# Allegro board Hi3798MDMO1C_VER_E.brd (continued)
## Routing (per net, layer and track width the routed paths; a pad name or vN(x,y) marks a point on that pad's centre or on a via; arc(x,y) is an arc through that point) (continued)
$4N687: length 3.1
  TOP w0.508: U11.1 96.09,54.12 C8.1 R73.2
$4N714: length 4.2
  TOP w0.508: U13.6 82.67,23.38 R110.1 83.93,23.38 R13.2 R101.1 C82.1
$4N715: length 94.6
  TOP w0.127: R23.1 80.94,55.4 80.58,55.75 C72.1 80.58,56.45 82.26,58.12 106.79,58.12 109.23,55.68 109.23,49.07 112.11,46.19 112.11,40.6 109.23,37.72 109.23,26.54 100.06,17.36 90.19,17.36 85.88,21.67 R102.2 84.3,21.67 84.28,21.69 C45.1
$4N716: length 0.9
  TOP w0.127: R102.1 84.75,22.54 R110.2
$4N724: length 3.9
  TOP w0.508: v1(82.55,27.01) 82.47,26.93 U13.1
  BOTTOM w0.508: v1(82.55,27.01) 82.55,26.98 82.97,26.57 R5.2 83.93,26.57 C5.1
$4N894: length 1.4
  TOP w0.508: R70.2 95.79,56.45 R7.1
$4N901: length 4
  TOP w0.508: U14.5 11.27,57.83 10.82,57.37 R100.1 10.8,56.83 9.77,56.83 R105.1
$4N903: length 5.9
  TOP w0.254: v1(15.09,66.33) 15.08,66.32 U14.1
  BOTTOM w0.254: v1(17.14,64.63) 17.14,65.14 15.95,66.33 v1(15.09,66.33) 14.59,66.84 R95.1
$4N904: length 0.9
  TOP w0.254: R104.1 12.69,55.89 C83.2
$4N905: length 3.9
  TOP w0.254: U14.6 12.54,58.27 11.89,57.62 C24.1 C83.1
$4N906: length 3.3
  TOP w0.254: R4.2 14.53,57.22 13.81,57.93 U14.7
$4N919: length 2.9
  TOP w0.254: U14.8 15.08,58.35 C44.1
$4N923: length 0.9
  BOTTOM w0.254: R95.2 13.14,67.65 C65.1
$4N925: length 1.6
  BOTTOM w0.254: C65.2 11.52,66.82 v1(11.52,66.83)
$5N541: length 3.6
  TOP w0.305: R144.2 20.28,58.19 21.11,57.37 Q4.3 22.28,56.91 R118.2
$5N542: length 100.2
  TOP w0.127: v2(21.41,49.88) 21.31,49.98 21.31,52.33 23.5,54.51 23.5,57.67 R118.1 22.86,58.79 22.23,59.43 22.23,60.72 22.03,60.91 Q14.1 ; v1(60.96,11.55) 60.81,11.7 27.53,11.7 16.05,23.18 v1(15.49,23.18)
  TOP w0.203: Q13.1 64.28,11.69 v1(64.14,11.55)
  TOP w0.254: Q14.1 21.36,62.74 C6.2 ; v2(17.27,41.91) 16.81,41.45 16.81,33.06 v2(16,32.25)
  BOTTOM w0.127: v1(15.49,23.18) 15.49,31.74 v2(16,32.25) ; v2(21.41,49.88) 21.31,49.77 21.31,48.17 17.27,44.13 17.27,42.31 17.27,42.31 v2(17.27,41.91)
  BOTTOM w0.203: v1(60.96,11.55) v1(64.14,11.55)
$5N549: length 1.4
  TOP w0.254: R98.2 20.04,53.74 20.09,53.79 Q4.1
$6N188: length 2.8
  TOP w0.203: X2.3 81.18,40.11 C365.1 80.3,39.11 R14.2
$6N1407: length 1.9
  TOP w0.305: U1.E6 v2(61.22,52.23)
  BOTTOM w0.381: v2(61.22,52.23) 61.04,52.41 R173.1
$6N2001: length 2.4
  TOP w0.127: U1.Y17 v2(70.82,40.23)
  BOTTOM w0.127: R61.2 71.33,39.05 71.22,39.16 71.22,39.84 v2(70.82,40.23)
$6N2177: length 6.7
  TOP w0.127: R85.1 R24.1 77.21,47.39 72.38,47.39 U1.L19
$6N2378: length 2.4
  TOP w0.127: U1.N23 76.36,45.43 76.83,45.91 R68.2
$7N1408: length 1.2
  TOP w0.127: U1.G17 v2(70.82,50.63)
  BOTTOM w0.127: v2(70.82,50.63) 70.69,50.76 C250.2
$7N1639: length 3.8
  TOP w0.127: U1.D8 v2(63.62,53.04)
  BOTTOM w0.127: R82.2 65,54.92 64.64,54.56 R87.2 64.07,53.48 v2(63.62,53.04)
$7N1763: length 1.3
  TOP w0.127: U1.F20 v2(73.22,51.43)
  BOTTOM w0.127: v2(73.22,51.43) 73.37,51.59 R32.2
$7N1940: length 49.5
  TOP w0.127: v1(106.73,59.05) 79.84,59.05 78.89,58.11 R42.1 ; S2.1 112.52,54.77 112.1,55.19 112.1,57.92 111.51,58.5 v1(111.51,59.84) 111.51,60.5 111.98,60.97 S2.2 113.32,61.85 114.68,63.21 C34.1
  BOTTOM w0.127: v1(111.51,59.84) 110.73,59.05 v1(106.73,59.05)
$8N1506: length 1.3
  TOP w0.127: U1.W16 v2(69.22,40.24)
  BOTTOM w0.127: R45.1 69.17,40.29 v2(69.22,40.24)
$8N1694: length 11
  TOP w0.152: U1.AC8 63.21,37.43 63.21,37.06 63.32,36.95 63.32,36.65 63.18,36.51 63.06,36.51 62.92,36.36 62.92,36.16 63.06,36.02 63.18,36.02 63.32,35.88 63.32,35.74 63.18,35.6 63.06,35.6 62.92,35.46 62.92,35.26 63.06,35.12 63.18,35.12 63.32,34.98 63.32,34.62 63.14,34.44 63.14,34.14 63.32,33.97 63.32,33.75 63.14,33.58 63.14,33.3 63.32,33.12 63.32,28.38 63.16,28.23 R18.2
$8N1695: length 10.9
  TOP w0.152: U1.AB8 63.22,38.03 63.62,37.63 63.62,28.29 63.34,28.01 R35.2
$8N1696: length 12.3
  TOP w0.152: R36.2 59.99,27.97 62.11,30.1 62.11,36.96 62.29,37.13 62.29,37.74 62.06,37.97 62.06,38.46 62.42,38.82 U1.AA7
$8N1697: length 11.9
  TOP w0.152: R37.2 60.93,27.6 60.93,27.88 60.76,28.06 60.76,28.31 62.42,29.97 62.42,36.83 62.59,37.01 62.59,37.88 62.42,38.05 U1.AB7
$9N2352: length 1.4
  TOP w0.305: U1.T19 v2(72.42,43.44)
  BOTTOM w0.381: C255.2 72.87,42.98 v2(72.42,43.44)
$11N1183: length 1.3
  TOP w0.165: U3.L8 v2(42.21,43.83)
  BOTTOM w0.127: R46.2 41.99,44.05 v2(42.21,43.83)
$11N1256: length 4.7
  BOTTOM w0.381: R15.1 46.42,39.46 45.81,38.84 44.63,38.84 44.23,39.24 C328.1 R11.2
$12N1465: length 2.9
  TOP w0.127: U6.L8 42.21,27.42 v2(42.21,28.22)
  BOTTOM w0.127: R71.2 41.15,28.5 41.43,28.22 v2(42.21,28.22)
$12N1636: length 4.1
  BOTTOM w0.203: R17.1 44.96,29.29 44.96,28.7 44.63,28.37 43.34,28.37 R16.2
  BOTTOM w0.254: R17.1 44.84,29.87 44.79,29.92 C330.1
$13N604: length 2.9
  TOP w0.089: U22.K2 100.91,31.25 101.57,31.25
  TOP w0.127: v2(101.59,31.25) 101.57,31.25
  BOTTOM w0.203: C124.1 100.96,31.89 v2(101.59,31.25) 101.97,31.63 C123.1
$13N727: length 2.9
  TOP w0.127: U19.39 99.16,22.88 v1(99.31,22.72)
  BOTTOM w0.127: R57.1 98.91,22.32 v1(99.31,22.72)
$13N772: length 2.1
  TOP w0.127: v2(98.64,22.82) 98.66,22.85 U19.38
  BOTTOM w0.127: R80.2 99.29,23.46 98.65,22.82 v2(98.64,22.82)
$14N447: length 2.2
  TOP w0.254: U26.3 83.05,72.06 v1(83.34,71.78)
  BOTTOM w0.254: R220.1 83.02,71.45 v1(83.34,71.78)
$14N448: length 3.3
  TOP w0.254: U26.4 79.65,72.35 v1(80.34,73.04)
  BOTTOM w0.254: v1(80.34,73.04) 81.38,72 R106.2
$14N684: length 4.2
  TOP w0.203: C70.1 73.03,68.06 J28.9
$14N685: length 5.3
  TOP w0.203: C62.1 69.62,69.08 70,68.7 70,68.57 70.18,68.39 73.13,68.39 73.51,68.77 J28.8
$15N955: length 5.2
  BOTTOM w0.254: Q2.1 100.74,9.96 99.39,9.96 99.39,9.97 98.68,9.97 R31.2
$15N957: length 1.8
  TOP w0.127: Q1.1 114.95,14.69 R22.2
$16N873: length 8.9
  TOP w0.254: R66.1 R90.2 92.98,64.75 C363.1 92.82,64.86 R229.1 90.93,65.45 90.93,67.17 91.5,67.74 U5.5
$16N884: length 3.4
  TOP w0.254: C32.1 95.05,66.44 U5.7
$16N889: length 2.1
  TOP w0.254: C33.2 91.88,67.09 U5.6
$16N895: length 2.7
  TOP w0.254: U5.8 98.45,66.44 C32.2
$16N998: length 2
  TOP w0.254: R43.2 102.26,66.58 R48.2 102.27,66.58 R44.1
$16N1000: length 2.5
  TOP w0.254: U5.11 100.51,68.39 R43.1
$16N1002: length 1.3
  TOP w0.254: R193.1 89.47,65.6 C351.2
$16N1003: length 3.7
  TOP w0.254: U5.2 92.19,69.69 91.93,69.43 C55.1 90.07,69.43 R27.2
$16N1006: length 3.7
  TOP w0.254: R27.1 R19.1 88.37,68.01 C317.1 88.37,66.92 R193.2
$16N1021: length 8.5
  TOP w0.254: v1(95,69.46) 95,69.43 94.61,69.04 U5.3 92.35,69.04 91.93,68.62 C55.2 90.86,68.62 90.38,68.14 R19.2
  BOTTOM w0.254: R146.1 93.36,70.03 R74.2 94.41,70.05 v1(95,69.46)
$16N1028: length 3.2
  TOP w0.254: R28.1 102.26,69.79 C54.2 100.64,69.79 100.55,69.69 U5.13
$16N1029: length 7.7
  TOP w0.254: R20.1 102.08,68.53 101.64,68.97 C54.1 100.31,68.97 100.24,69.04 U5.12 98.3,69.04 v1(97.69,69.65)
  BOTTOM w0.254: R145.1 99,70.04 R72.1 98.09,70.05 v1(97.69,69.65)
$16N1040: length 14.7
  TOP w0.254: R194.2 105.27,70.75 105.27,63.65 103.13,61.51 C350.1
$16N1041: length 4
  TOP w0.254: R20.2 R28.2 103.05,70.75 C316.1 R194.1
$17N163: length 3.5
  TOP w0.508: T2.7 v1(48.9,64.62)
  BOTTOM w0.381: C297.1 48.42,64.13 v1(48.9,64.62) 49.38,64.13 C154.1
$17N165: length 3.7
  TOP w0.381: R67.1 38.08,73.62 38.56,74.11 38.56,74.59 38.43,74.71 J25.9
$17N170: length 9.4
  TOP w0.381: R79.1 53.52,72.09 J25.11
$17N171: length 12.9
  BOTTOM w0.508: R270.2 47.82,75.06 47.82,79.54 J25.8 47.83,81.58 J25.7
$17N172: length 4.7
  TOP w0.457: v1(41.29,70.34) 42.11,70.34 42.55,70.78 T2.15
  BOTTOM w0.508: v1(41.29,70.34) 41.29,71.15 41.84,71.7 R271.2
$17N173: length 4.7
  TOP w0.457: T2.10 48.9,70.78 48.46,70.34 v1(47.64,70.34)
  BOTTOM w0.508: R269.2 48.19,71.7 47.64,71.15 v1(47.64,70.34)
$17N175: length 12.4
  TOP w0.254: T2.9 50.17,72.68 49.81,73.03 47.95,73.03 46.53,74.45 46.23,74.76 46.23,77.72 46.61,78.11 46.99,78.11 47.2,78.31 47.2,78.8 46.82,79.18 J25.6
$17N176: length 12.6
  TOP w0.254: T2.11 47.63,72.78 46.36,74.05 45.82,74.59 45.82,80.85 44.33,82.35 J25.3
$17N177: length 13.4
  BOTTOM w0.508: R270.1 51.02,69.69 49.11,69.69 R269.1 48.79,69.69 45.68,69.69 R272.1 45.36,69.69 42.76,69.69 R271.1 42.44,69.69 39.38,69.69 C23.1
$17N178: length 14.1
  TOP w0.254: J25.1 41.74,81.2 41.41,80.87 41.41,78.53 44.18,75.76 44.18,73.77 43.57,73.16 41.89,73.16 41.28,72.55 T2.16
$17N179: length 11
  TOP w0.254: J25.2 42.75,79.68 42.5,79.43 42.02,79.43 41.81,79.22 41.81,78.7 44.58,75.93 44.58,73.6 43.82,72.84 T2.14
$17N180: length 11.4
  BOTTOM w0.508: R272.2 45.52,77.6 44.78,78.33 J25.4 44.78,81.33 J25.5
$17N184: length 3.5
  TOP w0.508: T2.2 v1(42.55,64.62)
  BOTTOM w0.381: C307.1 43.03,64.13 v1(42.55,64.62) 42.07,64.13 C153.1
$17N255: length 6
  TOP w0.152: T2.1 41.28,62.29 v1(41.91,61.66)
  BOTTOM w0.152: R59.2 44.88,60.26 44.88,60.54 44.76,60.67 42.62,60.67 42.25,61.04 42.25,61.48 42.08,61.66 v1(41.91,61.66)
$17N256: length 6.2
  TOP w0.152: v1(43.18,61.69) 43.82,62.33 T2.3
  BOTTOM w0.152: R62.2 45.19,60.24 45.19,60.67 44.88,60.98 42.75,60.98 42.56,61.17 42.56,61.43 42.81,61.69 v1(43.18,61.69)
$17N257: length 5.3
  TOP w0.152: v1(48.28,61.69) 48.1,61.69 47.63,62.16 T2.6
  BOTTOM w0.152: R63.2 47.04,60.26 47.04,60.65 47.35,60.97 48.61,60.97 48.8,61.16 48.8,61.46 48.56,61.69 v1(48.28,61.69)
$17N258: length 5.3
  TOP w0.152: v1(49.55,61.72) 49.72,61.72 50.17,62.17 T2.8
  BOTTOM w0.152: R64.2 47.35,60.24 47.35,60.53 47.48,60.66 48.73,60.66 49.1,61.03 49.1,61.52 49.3,61.72 v1(49.55,61.72)
$19N506: length 2
  TOP w0.254: D19.1 28.26,68.59 29.17,69.49 R268.1

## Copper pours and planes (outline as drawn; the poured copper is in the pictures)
1V1_CORE on TOP (solid shape): 82.42,32.88 82.42,31.49 81.96,31.02 78.45,31.02 78.23,30.81 78.23,26.91 77.98,26.66 76.23,26.66 76.11,26.79 76.11,33.1 76.26,33.25 82.06,33.25
1V1_CORE on TOP (solid shape): 68.54,48.79 68.54,48.76 68.54,48.75 68.52,48.62 68.55,48.49 68.56,48.47 68.56,47.99 68.55,47.98 68.52,47.83 68.55,47.69 68.56,47.67 68.56,47.19 68.55,47.18 68.52,47.03 68.55,46.89 68.56,46.87 68.56,46.39 68.55,46.38 68.52,46.23 68.55,46.09 68.56,46.07 68.56,45.59 68.55,45.58 68.52,45.43 68.55,45.29 68.56,45.27 68.56,45.24 69.23,44.56 69.23,43.7 70.21,42.72 71.15,42.72 72.09,41.78 72.09,41.02 72.01,40.94 71.96,40.93 71.91,40.92 71.33,40.92 71.28,40.93 70.36,40.93 70.31,40.92 69.93,40.92 66.4,44.45 64.75,44.45 64.57,44.63 64.57,46.53 64.68,46.78 64.57,47.02 64.57,47.15 64.65,47.23 65.27,47.23 65.32,47.18 65.33,47.16 65.33,47.13 65.32,46.98 65.39,46.84 65.39,46.43 65.32,46.23 65.39,46.04 65.39,45.95 65.46,45.87 66.63,45.87 66.71,45.95 66.71,46.13 66.73,46.23 66.71,46.34 66.71,46.93 66.73,47.03 66.71,47.14 66.71,47.73 66.86,47.88 66.88,47.88 67.16,48.12 67.08,48.48 67.08,48.48 67.06,48.52 67.06,48.74 67.14,48.82 68.51,48.82
1V1_CORE on BOTTOM (solid shape): 72.65,42.01 72.65,41.51 73.26,40.91 73.76,40.91 74.5,40.16 74.5,40.15 78.62,36.04 78.62,33.57 79,33.19 79,31.39 78.77,31.16 76.01,31.16 75.83,31.34 75.83,33.52 78.23,33.52 78.23,33.9 77.85,33.9 77.85,33.52 75.83,33.52 75.83,34.13 78.18,34.13 78.18,34.46 77.85,34.46 77.85,34.13 75.83,34.13 75.83,34.77 74.81,35.79 74.81,37.71 73.41,39.11 74.42,39.11 74.42,38.98 74.55,38.85 74.68,38.85 74.8,38.98 74.8,39.11 74.68,39.23 74.55,39.23 74.42,39.11 73.41,39.11 72.57,39.95 72.4,39.95 71.78,40.57 70.71,40.57 69.77,41.52 69.77,42.07 69.78,42.09 70.62,42.09 70.72,42.19 70.72,42.77 70.77,42.82 71.84,42.82
1V1_CORE on BOTTOM (solid shape): 67.7,49.1 67.7,48.51 67.77,48.44 68.59,48.44 68.66,48.36 68.66,45.72 67.8,44.86 66.17,44.86 65.67,44.35 65.67,44.14 64.93,44.14 64.83,44.25 64.57,44.25 64.54,44.25 64.5,44.26 64.45,44.25 64.42,44.25 64.27,44.25 64.24,44.27 64.24,44.44 65.02,44.44 65.02,44.69 64.64,44.69 64.64,44.44 64.24,44.44 64.24,44.73 64.72,45.2 67.44,45.2 67.44,45.58 66.67,45.58 66.67,45.2 64.72,45.2 64.93,45.41 64.93,46.85 65.41,46.85 65.41,47.11 65.15,47.11 65.15,46.85 64.93,46.85 64.93,47.5 64.98,47.55 65.49,47.55 65.64,47.4 65.64,46.23 65.78,46.09 67.13,46.09 67.16,46.13 67.16,46.6 67.69,46.6 67.69,46.73 68.33,46.73 68.33,47.11 67.94,47.11 67.94,46.73 67.69,46.73 67.69,47.36 67.44,47.36 67.44,46.6 67.16,46.6 67.16,48.14 67.17,48.17 67.18,48.24 67.17,48.3 67.16,48.33 67.16,48.94 67.18,49.04 67.19,49.07 67.21,49.1 67.23,49.11 67.26,49.12 67.28,49.12 67.67,49.12
1V1_CPU on TOP (solid shape): 93.5,53.3 93.5,48.86 93.13,48.49 86.43,48.49 86.17,48.75 86.17,53.01 86.18,53.02 86.18,53.28 86.63,53.73 93.07,53.73
1V1_CPU on TOP (solid shape): 71.05,49.62 71.05,46.53 70.63,46.11 70.58,46.07 70.52,46 69.42,46 69.37,46.05 69.37,47.32 69.48,47.42 69.7,47.42 69.86,47.57 69.86,47.64 69.87,47.65 69.93,47.83 69.87,48.02 69.86,48.03 69.86,48.11 69.7,48.26 69.42,48.26 69.37,48.31 69.37,48.71 69.38,48.73 69.4,48.75 69.56,49.04 69.4,49.32 69.38,49.34 69.37,49.37 69.37,49.48 69.69,49.8 70.87,49.8
1V1_CPU on BOTTOM (solid shape): outline of 82 points within 69.81,46.04 90.68,50.97
1V5_DDR3 on TOP (solid shape): 17.64,53.6 18.23,53 18.23,46.8 17.88,46.45 15.32,46.45 15.26,46.51 15.26,48.25 17.78,48.25 17.78,48.5 17.4,48.5 17.4,48.25 15.26,48.25 15.26,48.69 15.2,48.76 17.78,48.76 17.78,49.14 17.4,49.14 17.4,48.76 15.2,48.76 15.08,48.87 15.08,53.33 15.35,53.6 16.82,53.6
1V5_DDR3 on TOP (solid shape): outline of 110 points within 59.77,39.68 68.23,48.84
1V5_DDR3 on BOTTOM (solid shape): 64.6,42.82 64.6,41.99 64.67,41.93 64.8,41.93 64.81,41.94 66.55,41.94 66.66,42.04 68.49,42.04 68.51,42.01 68.51,41.48 68.49,41.45 67.9,41.45 67.85,41.4 63.41,41.4 63.35,41.45 63.35,42.8 63.43,42.87 64.55,42.87
1V5_DDR3 on BOTTOM (solid shape): outline of 624 points within 16.71,24.44 62.36,53.76
3V3 on TOP (solid shape): 121.79,40.85 121.79,20.82 119.35,18.38 119.35,17.16 119.1,16.91 117.53,16.91 117.31,17.12 117.31,18.85 119.58,21.13 119.58,40.85 119.74,41.01 121.64,41.01
3V3 on TOP (solid shape): 80.91,23.83 80.91,22.72 80.75,22.57 80.24,22.57 80.14,22.47 80.14,22.35 80.14,22.34 80.14,21.28 80.07,21.21 76.63,21.21 76.56,21.28 76.39,21.45 76.39,21.71 79.63,21.71 79.63,22.09 79.38,22.09 79.38,21.71 76.39,21.71 76.39,23.79 76.54,23.94 80.8,23.94
3V3 on TOP (solid shape): 107.58,54.77 107.58,51.56 106.02,50 99.98,50 99.79,50.19 99.79,50.38 101.19,50.38 101.19,50.69 100.94,50.69 100.94,50.38 100.66,50.38 100.66,50.69 100.41,50.69 100.41,50.38 99.79,50.38 99.79,51.27 99.54,51.52 99.54,52.47 99.57,52.49 105.24,52.49 105.63,52.88 105.63,54.74 105.81,54.93 107.42,54.93
3V3 on TOP (solid shape): 9.22,62.08 9.22,60.12 8.82,59.73 6.38,59.73 5.94,59.3 5.94,54.54 6.51,53.98 6.51,50.88 6.85,50.54 8.51,50.54 8.64,50.41 8.64,49.52 8.51,49.39 5.72,49.39 5.46,49.13 4.56,48.23 4.56,48.23 3.89,47.56 3.89,41.05 3.63,40.78 1.72,40.78 1.45,41.05 1.45,49.77 6.1,49.77 6.1,50.15 5.71,50.15 5.71,49.77 1.45,49.77 1.45,54.6 5.59,54.6 5.59,54.98 5.21,54.98 5.21,54.6 1.45,54.6 1.45,55.11 5.59,55.11 5.59,55.49 5.21,55.49 5.21,55.11 1.45,55.11 1.45,58.81 4.94,62.31 8.98,62.31
3V3 on TOP (solid shape): 111.35,14.62 111.35,13.32 111.18,13.15 110.21,13.15 105.78,8.72 105.68,8.71 105.59,8.71 99.94,8.71 99.94,8.71 99.14,8.58 98.53,8.06 98.51,8.05 98.49,8.04 96.71,8.04 96.69,8.04 81.69,8.04 81.69,8.04 80.8,8.04 80.78,8.05 80.76,8.06 80.15,8.58 79.36,8.7 79.35,8.7 73.7,8.7 73.7,8.7 72.91,8.58 72.29,8.06 72.28,8.05 72.25,8.04 70.13,8.04 70.13,8.04 68.17,8.04 67.68,8.53 67.67,8.53 67.36,8.84 64.73,8.84 64.51,9.06 64.51,10.65 64.69,10.83 66.89,10.83 67.33,11.27 67.33,12.17 67.56,12.39 68.67,12.39 68.91,12.15 68.91,10.4 69.43,9.89 103.85,9.89 108.72,14.76 108.74,14.76 108.88,14.9 111.07,14.9
3V3 on BOTTOM (solid shape): 121.88,45.28 121.88,39.84 121.63,39.59 119.7,39.59 119.53,39.76 119.53,43.96 112.83,50.66 105.28,50.66 104.95,50.99 104.95,52.26 105.28,52.59 114.56,52.59
3V3 on BOTTOM (solid shape): 119.39,18.45 119.39,17.3 119.39,17.3 119.39,14.37 119.19,14.16 111.95,14.16 110.93,13.15 109.35,13.15 108.79,13.71 108.79,15.23 111.2,17.64 117.12,17.64 117.32,17.85 117.32,18.48 117.45,18.61 119.23,18.61
3V3 on BOTTOM (solid shape): 3.89,42.18 3.89,27.67 20.73,10.83 20.9,10.66 64.68,10.66 64.85,10.83 65.9,10.83 77.98,10.83 78.21,10.83 78.5,11.12 78.5,20.93 78.18,21.25 77.87,21.25 77,22.11 77,22.75 77.18,22.93 80.8,22.93 80.93,22.8 80.93,8.95 80.92,8.93 80.72,8.73 78.92,8.73 78.76,8.88 19.45,8.88 1.44,26.89 1.44,42.15 1.8,42.51 3.56,42.51
3V3_IR on TOP (solid shape): 121.29,15.62 122.43,15.62 122.69,15.37 122.69,8.94 122.48,8.73 120.97,8.73 120.59,9.11 120.59,13.31 120.47,13.43 119.38,13.43 118.5,14.31 118.5,14.85 121.79,14.85 121.79,15.23 121.41,15.23 121.41,14.85 119.38,14.85 119.38,15.23 119,15.23 119,14.85 118.5,14.85 118.5,15.37 118.62,15.49 119.26,15.49 119.77,16 120.91,16
3V3_MOS on TOP (solid shape): 16.64,18.28 16.64,17.52 15.88,17.52 14.86,18.53 14.86,18.66 15.24,19.04 15.88,19.04
3V3_MOS on TOP (solid shape): 114.88,69.54 114.88,69.13 115.46,68.55 115.46,65.74 115.34,65.62 113.87,65.62 113.79,65.7 113.79,69.59 113.87,69.66 114.76,69.66
3V3_MOS on TOP (solid shape): 111.51,57.77 111.51,50.99 115.19,47.31 115.19,44.69 114.86,44.36 113.23,44.36 112.9,44.7 112.9,46.37 109.98,49.29 109.98,56.88 109.98,56.88 105.78,61.08 105.78,61.82 106.17,62.21 107.07,62.21
3V3_MOS on TOP (solid shape): 118.67,38.14 118.67,25.42 103.4,10.15 72.29,10.15 72.14,10.3 72.14,10.3 69.92,12.52 66.44,12.52 66.37,12.59 66.37,14.34 66.68,14.65 70.75,14.65 74.13,11.28 96.16,11.28 96.37,11.21 96.57,11.28 102.01,11.28 107.59,16.86 107.62,16.86 109.15,18.39 109.3,18.48 109.39,18.62 116.48,25.72 116.48,38.12 116.79,38.42 118.39,38.42
3V3_MOS on TOP (solid shape): outline of 100 points within 60.64,45.24 72.68,52.81
3V3_MOS on BOTTOM (solid shape): 63.58,50.44 63.58,48.69 63.57,48.68 62.77,48.68 62.72,48.73 62.72,49.87 62.41,50.18 62.41,50.44 62.5,50.53 63.49,50.53
3V3_MOS on BOTTOM (solid shape): 74.56,46.02 74.56,44.61 74.46,44.51 73.73,44.51 73.66,44.59 73.65,44.59 73.63,44.6 73.63,45.27 73.41,45.49 72.27,45.49 72.17,45.59 72.17,46 72.22,46.05 74.53,46.05
3V3_MOS on BOTTOM (solid shape): 64.78,52.3 64.78,51.41 64.55,51.18 63.4,51.18 63.38,51.2 63.38,51.75 63.42,51.79 63.89,51.79 64.14,52.04 64.14,52.32 64.75,52.32
3V3_MOS on BOTTOM (solid shape): 118.69,42.19 118.69,36.74 118.52,36.57 116.48,36.57 116.31,36.74 116.31,40.81 113.26,43.86 111.25,43.86 109.52,42.13 106.94,42.13 106.76,42.31 106.76,43.63 109.26,46.13 114.76,46.13
3V3_MOS on BOTTOM (solid shape): 59.98,52.88 59.98,51.99 60.1,51.87 61.35,51.87 61.45,51.76 61.45,51.36 61.3,51.21 61.12,51.21 60.87,51.46 59.44,51.46 59.42,51.49 59.42,52.86 59.47,52.91 59.95,52.91
3V3_MOS on BOTTOM (solid shape): 66.01,53.76 66.01,53.35 66.17,53.19 66.66,53.19 66.68,53.16 66.68,52.63 67.06,52.25 67.06,51.84 66.99,51.76 65.95,51.76 65.92,51.79 65.92,52.96 65.64,53.24 65.28,53.24 65.26,53.26 65.26,53.8 65.31,53.85 65.92,53.85
3V3_MOS on BOTTOM (solid shape): outline of 88 points within 71.2,49.64 107.48,62.97
3V3_MOS_FLASH on TOP (solid shape): outline of 288 points within 92.84,30.17 109.38,42.85
3V3_MOS_FLASH on BOTTOM (solid shape): 110.19,41.19 110.19,39.57 109.74,39.12 105.5,39.12 105.32,39.3 105.32,41.06 105.59,41.32 110.06,41.32
3V3_MOS_FLASH on BOTTOM (solid shape): 95.96,30.83 95.96,30.46 95.86,30.37 94.51,30.37 92.12,27.98 92.12,26.33 93.97,24.49 96.79,24.49 96.9,24.37 96.9,23.99 97.03,23.87 97.92,23.87 98.04,23.99 98.04,24.5 98.17,24.63 99.44,24.63 99.57,24.5 99.57,23.99 99.44,23.87 98.93,23.87 98.68,23.61 98.68,23.36 98.17,22.85 96.9,22.85 96.65,22.6 96.27,22.6 96.01,22.85 94.11,22.85 93.73,22.47 93.73,21 94.08,20.64 102.18,20.64 102.39,20.44 102.39,19.73 102.08,19.42 91.14,19.42 90.8,19.75 90.8,21.73 91.05,21.97 91.31,21.97 91.95,22.61 91.95,23.1 91.82,23.23 97.79,23.23 97.79,23.61 97.41,23.61 97.41,23.23 91.82,23.23 91.11,23.95 91.11,28.62 93.41,30.93 95.85,30.93
3V3_WIFI on TOP (solid shape): 14.4,31.8 14.4,30.11 12.14,27.85 9.78,27.85 9.51,28.12 9.51,29.09 9.74,29.31 11.88,29.31 12.75,30.18 12.75,31.74 12.99,31.97 13.13,31.97 13.13,31.98 14.23,31.98
3V3_WIFI on BOTTOM (solid shape): 7.84,37.43 7.84,32.75 6.96,31.87 6.96,30.49 8.1,29.35 8.45,29.35 8.45,29.36 11.81,29.36 12.46,28.7 12.46,27.56 12.81,27.21 14.18,27.21 14.36,27.02 14.36,26.15 14.07,25.86 11.56,25.86 10.31,27.12 7.84,27.12 5.41,29.55 5.41,32.54 6.1,33.23 6.1,37.43 6.54,37.87 7.4,37.87
5V0 on TOP (solid shape): 15.18,73.01 15.18,71.99 16.11,71.06 18.62,71.06 19.23,70.45 19.23,66.77 20.68,65.32 20.68,61.45 20.46,61.24 18.12,61.24 17.78,61.57 17.78,63.46 18.67,64.35 18.67,65.45 17.78,66.33 17.78,68.7 17.65,68.82 16.13,68.82 15.98,68.68 15.98,66.85 15.81,66.67 15.22,66.67 15.19,66.68 15.14,66.69 15.09,66.7 15.04,66.69 14.99,66.68 14.96,66.67 14.66,66.67 14.4,66.41 14.4,63.84 13.52,63.84 13.51,63.84 13.41,63.84 13.41,68.32 14.22,68.32 14.22,68.7 13.84,68.7 13.84,68.32 13.41,68.32 13.41,68.74 12.53,69.62 8.4,69.62 8.24,69.77 8.24,70.09 11.05,70.09 11.05,70.35 10.79,70.35 10.79,70.09 10.54,70.09 10.54,70.35 10.29,70.35 10.29,70.09 8.24,70.09 8.24,73.57 8.51,73.84 14.35,73.84
5V0_MOS on TOP (solid shape): 21.88,60.49 21.88,59.23 21.68,59.03 19.16,59.03 18.99,59.2 18.99,60.45 19.14,60.6 21.77,60.6
5V0_MOS on TOP (solid shape): 84.68,71.03 84.68,69.2 84.3,68.82 82.1,68.82 81.56,69.36 81.56,70.4 81.69,70.53 83.24,70.53 83.79,71.08 84.63,71.08
5V0_MOS on BOTTOM (solid shape): 81.6,82.63 81.6,80.09 82.95,78.74 82.95,78.74 83.35,78.34 83.36,78.34 85.66,76.04 85.66,69.77 84.71,68.82 82.53,68.82 82.53,69.68 82.06,70.15 82.06,70.22 82.93,70.22 82.93,70.6 82.55,70.6 82.55,70.22 82.06,70.22 82.06,70.88 82.17,70.98 84.33,70.98 84.64,71.29 84.64,73.86 84.64,73.86 84.64,75.64 80.52,79.76 80.52,82.16 80.12,82.56 62.21,82.56 62.21,82.56 61.86,82.56 58.4,79.1 58.4,68.32 57.37,67.29 54.99,67.29 54.1,66.4 38.73,66.4 33.37,61.04 24.32,61.04 24.05,60.78 22.19,58.92 19.07,58.92 18.81,59.18 18.81,60.34 19.14,60.67 21.44,60.67 23.7,62.94 32.57,62.94 37.09,67.46 53.56,67.46 54.5,68.39 56.33,68.39 57.01,69.08 57.01,70.9 57.01,70.9 57.01,79.45 61.11,83.56 80.68,83.56
AVDD11_PLL012 on BOTTOM (solid shape): 70.36,45.9 70.36,45.34 70.51,45.2 71.15,45.2 71.22,45.13 71.22,44.31 71.25,44.29 71.59,44.29 71.61,44.27 71.61,43.59 71.58,43.56 70.77,43.56 70.75,43.59 70.75,44.6 70.54,44.81 69.88,44.81 69.81,44.88 69.81,45.9 69.83,45.92 70.34,45.92
AVDD11_USB3 on TOP (solid shape): 69.83,43.89 70.16,43.89 70.26,43.99 70.57,43.99 70.62,43.94 70.62,42.93 70.54,42.85 70.29,42.85 69.42,43.71 69.42,43.84 69.58,43.99 69.73,43.99
AVDD11_USB3 on BOTTOM (solid shape): 70.24,43.51 70.24,42.95 70.31,42.87 70.31,42.39 70.28,42.35 69.74,42.35 69.65,42.44 68.61,42.44 68.23,42.82 68.23,44.01 68.35,44.13 69.62,44.13
AVDD33_ADAC on BOTTOM (solid shape): 71.93,55.4 71.93,54.71 72.14,54.5 72.14,53.49 72.27,53.37 72.85,53.37 72.85,52.37 72.47,51.99 72.37,51.99 72.35,52.02 72.27,52.06 72.2,52.17 72.19,52.22 72.2,52.3 72.21,52.31 72.21,52.41 72.04,52.58 71.48,52.58 71.47,52.59 71.29,52.59 71.2,52.68 71.2,53.31 71.03,53.49 71.03,55.33 71.2,55.5 71.83,55.5
AVDD33_PLL01 on BOTTOM (solid shape): 76.03,46 76.03,43.76 75.77,43.51 73.74,43.51 73.36,43.89 72.22,43.89 72.14,43.97 72.14,44.32 72.28,44.46 73.6,44.46 74.02,44.04 74.84,44.04 75.04,44.25 75.04,46.02 75.06,46.05 75.98,46.05
AVDD33_USB2 on BOTTOM (solid shape): 75.49,48.69 72.36,48.69 72.36,48.69 72.25,48.69 72.18,48.77 72.18,49.17 72.21,49.18 72.28,49.21 72.34,49.25 72.48,49.25 72.57,49.19 72.69,49.16 72.87,49.16 73.01,49.3 74.1,49.3 74.33,49.52 75.49,49.52
GND on TOP (solid shape): 34.51,45.79 34.51,45.74 28.83,40.07 28.61,40.07 28.57,40.08 28.56,40.12 28.56,40.19 29.41,41.04 29.41,41.32 34.12,46.04 34.26,46.04
GND on TOP (solid shape): 38.73,42.82 38.76,42.81 38.78,42.77 38.78,42.35 38.68,42.25 37.46,42.25 28.59,33.39 28.54,33.38 28.51,33.42 28.51,33.46 28.75,33.7 28.75,34.2 37.37,42.82
GND on TOP (solid shape): 39.17,40.72 39.26,40.65 39.24,40.54 28.6,29.91 28.56,29.91 28.52,29.92 28.51,29.96 28.51,30.11 28.8,30.4 28.8,30.78 38.73,40.72
GND on TOP (solid shape): 79.37,51.3 79.46,51.24 79.44,51.12 79.43,51.11 77.35,51.11 76.61,50.37 76.23,50.37 76.19,50.38 76.17,50.42 76.17,50.46 77.01,51.3
GND on TOP (solid shape): 80.3,46.19 98.82,46.19 99.97,45.04 99.97,44.89 99.71,44.63 99.64,44.63 98.6,45.68 80.03,45.68 80.03,45.68 79.56,45.68 79.46,45.74 79.49,45.86 79.82,46.19 80.29,46.19
GND on TOP (solid shape): 36.32,44.86 36.41,44.79 36.39,44.69 28.76,37.05 28.65,37.03 28.58,37.12 28.56,37.12 28.56,37.51 35.9,44.86
GND on TOP (solid shape): 112.34,58.69 113.1,58.69 113.1,57.04 112.29,57.04 112.29,58 111.7,58.58 111.7,59.51 111.9,59.84 111.7,60.17 111.7,60.42 112.06,60.78 112.34,60.78
GND on TOP (solid shape): 35.05,70.47 35.05,70.3 35.05,70.3 35.05,68.21 34.91,68.07 34.18,68.07 33.89,68.36 33.89,68.7 34.67,68.7 34.67,69.46 34.42,69.46 34.42,68.7 33.89,68.7 33.89,69.04 33.88,69.04 33.88,69.15 33.89,69.15 33.89,69.98 33.73,70.14 33.73,70.54 33.82,70.62 34.89,70.62
GND on TOP (solid shape): 90.09,38 90.09,20.52 90.02,20.43 89.91,20.45 89.49,20.87 89.49,37.86 84.39,42.96 77.61,42.96 77.52,43.03 77.54,43.14 77.93,43.52 84.56,43.52
GND on TOP (solid shape): 29.47,73.56 29.47,72.21 29.48,72.2 31.18,72.2 31.21,72.18 31.23,72.15 31.23,71.39 31.21,71.35 31.18,71.34 29.48,71.34 29.23,71.09 28.77,71.09 27.33,72.53 27.33,73.52 27.6,73.8 29.24,73.8
GND on TOP (solid shape): 92.16,66.06 92.56,66.06 92.56,66.06 94.42,66.06 94.47,66.06 94.59,66.19 94.95,66.19 95.89,65.25 95.89,64.7 97.61,64.7 97.61,65.25 98.43,66.06 99.9,66.06 99.9,66.06 100.72,66.06 100.9,65.87 100.9,65.15 100.9,64.08 100.9,63.91 100.9,63.63 100.68,63.63 100.12,64.19 95.49,64.19 95.49,65.2 93.71,65.2 93.46,65.46 93.46,65.47 92.27,65.47 92.12,65.47 91.97,65.32 91.42,65.32 91.22,65.52 91.95,65.52 91.95,65.78 91.57,65.78 91.57,65.52 91.22,65.52 91.19,65.55 91.19,66.26 91.96,66.26
GND on TOP (solid shape): 41.88,42.97 41.88,42.95 42,42.77 42.21,42.7 42.27,42.67 42.4,42.41 42.6,42.33 42.67,42.3 42.7,42.23 42.7,42.08 41.25,40.63 40.43,40.63 40.33,40.69 40.36,40.8 40.92,41.37 41.13,41.37 41.25,41.48 41.26,41.48 41.62,41.84 41.62,42.34 41.6,42.37 41.6,43.1 41.75,43.1
GND on TOP (solid shape): 60.11,44.12 60.11,44.11 60.17,44.01 60.25,43.94 60.25,43.73 60.13,43.6 60.08,43.44 60.06,43.37 59.99,43.34 59.88,43.31 59.79,43.24 59.45,43.24 59.29,43.33 59.1,43.32 59,43.32 58.96,43.35 58.96,43.35 58.63,43.68 58.36,43.68 58.29,43.76 58.29,43.93 58.34,43.99 58.8,43.99 58.92,43.87 58.92,43.85 59.38,43.57 59.36,44.11 59.36,44.36 59.4,44.38 59.45,44.38 59.54,44.48 59.74,44.48
GND on TOP (solid shape): 25.01,75.81 25.01,75.22 24.88,75.1 24.88,74.8 24.88,74.79 24.85,74.73 24.85,74.67 24.85,74.09 24.85,74.02 24.88,73.97 24.88,73.95 24.88,73.75 24.88,73.74 24.85,73.68 24.85,73.62 24.85,73.04 24.85,72.97 24.88,72.92 24.88,72.9 24.88,72.74 24.97,72.65 24.97,68.83 27.59,66.21 32.4,66.21 38.11,60.49 50.9,60.49 54.3,63.9 63.72,63.9 66.55,61.06 66.55,60.81 66.87,60.49 67.13,60.49 67.2,60.41 67.2,60.16 67.52,59.84 67.78,59.84 68.4,59.22 68.4,58.92 68.71,58.6 69.02,58.6 69.57,58.04 69.57,57.74 69.89,57.42 70.19,57.42 70.33,57.28 70.33,56.66 70.31,56.59 70.24,56.56 63.38,63.41 54.44,63.41 50.98,59.96 38.05,59.96 32.26,65.75 26.53,65.75 24.19,68.09 24.19,72.5 24.29,72.6 24.29,72.9 24.3,72.92 24.32,72.97 24.33,73.04 24.33,73.62 24.32,73.68 24.3,73.74 24.29,73.75 24.29,73.95 24.3,73.97 24.32,74.02 24.33,74.09 24.33,74.67 24.32,74.73 24.3,74.79 24.29,74.8 24.29,75.1 24.18,75.21 24.18,75.96 24.32,76.1 24.71,76.1
GND on TOP (solid shape): outline of 116 points within 74.99,23.68 86,37.95
GND on TOP (solid shape): outline of 89 points within 21.01,55.11 68.68,75.81
GND on TOP (solid shape): 26.75,75.48 26.75,72.56 28.69,70.63 28.68,70.63 29.04,70.27 29.04,69.73 27.99,68.68 27.5,68.68 27.5,67.77 28.77,67.77 28.77,67.76 29.95,67.76 30.32,67.39 32.92,67.39 37.1,63.2 37.1,63.18 37.34,62.75 37.8,62.91 37.9,62.91 38.15,62.73 38.45,62.79 38.55,62.8 38.61,62.71 38.61,62.35 38.82,62.14 38.81,62.11 39.06,61.68 39.53,61.86 40.84,61.86 40.84,61.88 41.4,61.88 41.55,61.73 41.55,61.71 41.62,61.45 41.84,61.3 41.88,61.3 41.88,61.2 41.61,61.2 41.6,61.2 38.41,61.2 32.69,66.92 27.89,66.92 25.68,69.13 25.68,72.6 25.79,72.71 25.79,72.77 25.81,72.8 25.82,72.81 25.89,72.92 25.92,73.05 25.92,73.61 25.9,73.72 25.85,73.81 25.83,73.85 25.85,73.89 25.9,73.99 25.92,74.1 25.92,74.66 25.89,74.78 25.82,74.89 25.81,74.9 25.79,74.94 25.79,75.1 25.68,75.21 25.68,75.8 25.85,75.97 26.27,75.97
GND on TOP (solid shape): outline of 153 points within 116.23,8.5 119.34,13.45
GND on TOP (solid shape): outline of 137 points within 96.39,31.13 100.04,35.85
GND on TOP (solid shape): outline of 19011 points within 0.51,7.62 123.52,86.57
GND on BOTTOM (solid shape): 41.11,43.64 41.11,42.92 40.32,42.92 39.94,43.29 39.94,43.96 40.04,44.06 40.69,44.06
GND on BOTTOM (solid shape): 56.75,79.07 56.75,69.28 56.51,69.03 55.09,69.03 55.05,69.08 55.05,77.92 55.49,78.36 56.28,79.16 56.67,79.16
GND on BOTTOM (solid shape): 71.96,8.58 71.96,7.69 71.91,7.63 51.56,7.63 51.46,7.74 51.46,8.5 51.59,8.63 66.15,8.63 71.9,8.63
GND on BOTTOM (solid shape): outline of 178 points within 97.99,34.96 103.03,42.07
GND on BOTTOM (solid shape): outline of 14253 points within 0.51,7.62 123.52,86.57
FE_3V3 on BOTTOM (solid shape): 59.8,53.8 60.48,53.8 60.64,53.64 60.64,52.07 60.56,51.99 60.28,51.99 60.2,52.07 60.2,53.06 60.13,53.14 59.24,53.14 59.19,53.09 59.19,52.37 59.16,52.35 58.68,52.35 58.66,52.37 58.66,54.08 58.71,54.13 59.47,54.13
HDMI_TX_1V1 on BOTTOM (solid shape): 69.6,52.07 69.6,51.56 69.12,51.08 69.12,50.42 69.22,50.32 69.55,50.32 69.63,50.24 69.63,49.52 69.54,49.43 68.76,49.43 68.71,49.38 68.71,48.67 68.66,48.62 67.95,48.62 67.95,49.7 67.98,49.83 67.95,49.97 67.95,50.14 67.9,50.19 67.32,50.19 67.29,50.22 67.29,50.96 67.33,51 68.28,51 69.04,51.76 69.04,52.07 69.07,52.1 69.58,52.1
HDMI_TX_3V3 on BOTTOM (solid shape): 67.04,53.87 67.04,53.39 67.29,53.14 68.51,53.14 68.66,52.98 68.66,52.18 68.63,52.15 68.61,52.11 68.58,52.07 68.49,52.02 68.42,52.01 68.36,52.02 68.3,52.04 68.25,52.08 68.21,52.12 68.18,52.16 68.18,52.58 68.13,52.63 66.88,52.63 66.81,52.7 66.81,53.24 66.58,53.47 66.17,53.47 66.17,53.97 66.94,53.97
Net_278 on BOTTOM (solid shape): 52.91,79.93 50.25,79.93 50.25,81.2 52.91,81.2
Net_279 on BOTTOM (solid shape): 41.36,79.93 38.69,79.93 38.69,81.2 41.36,81.2
Net_280 on BOTTOM (solid shape): 51.9,81.71 49.23,81.71 49.23,82.98 51.9,82.98
Net_281 on BOTTOM (solid shape): 40.34,81.71 37.67,81.71 37.67,82.98 40.34,82.98
USB01_1V1 on BOTTOM (solid shape): 65.64,50.06 65.78,50.06 65.78,50.06 66.18,50.06 66.25,49.99 66.25,49.68 66.17,49.61 65.61,49.61 65.51,49.5 65.51,47.78 65.49,47.75 64.95,47.75 64.93,47.78 64.93,50.22 64.95,50.24 65.46,50.24
USB01_3V3 on BOTTOM (solid shape): 63.1,54.25 63.1,51.21 63.07,51.18 62.54,51.18 62.47,51.26 62.47,53.21 62.14,53.54 62.14,54.29 62.18,54.33 63.02,54.33
USB03_VBUS on TOP (solid shape): 80.86,70.06 80.86,69.55 83.06,67.35 83.06,64.63 82.55,64.12 78.61,64.12 78.49,64.25 78.49,70.27 78.79,70.58 80.34,70.58
USB03_VBUS on BOTTOM (solid shape): 80.9,69.84 82.01,69.84 82.19,69.66 82.19,69.61 82.2,69.6 82.2,65.47 81.99,65.27 79.5,65.27 78.99,65.78 78.99,66.77 78.49,67.28 77.35,67.28 77.12,67.32 76.88,67.28 75.12,67.28 74.68,67.72 74.68,68.43 75,68.75 78.92,68.75 80.01,69.84 80.9,69.84
VDAC_3V3 on BOTTOM (solid shape): 76.51,53.42 76.51,52.6 76.46,52.55 74.98,52.55 74.97,52.56 74.82,52.59 74.67,52.56 74.57,52.49 74.51,52.4 74.19,52.08 73.43,52.08 73.12,51.78 73.11,51.77 72.97,51.69 72.88,51.55 72.88,51.54 72.59,51.24 72.55,51.24 72.52,51.23 72.42,51.21 72.32,51.23 72.23,51.31 72.19,51.42 72.19,51.45 72.2,51.5 72.24,51.59 72.54,51.88 72.57,51.91 72.58,51.92 72.67,51.98 72.74,52.08 72.75,52.09 73.43,52.77 73.46,52.8 74.14,52.8 74.35,53.01 74.35,53.47 74.38,53.49 76.44,53.49
$4N589 on TOP (solid shape): 14.03,53.51 14.03,49.84 13.84,49.65 10.03,49.65 9.88,49.8 9.88,50.54 10.2,50.86 10.47,50.86 11.05,51.44 11.05,53.01 11.7,53.67 13.87,53.67
$4N679 on TOP (solid shape): 96.82,52.52 98.35,52.52 98.47,52.39 98.47,49.85 98.47,49.85 98.47,49.2 98.32,49.06 94.93,49.06 94.72,49.27 94.72,52.87 94.77,52.92 96.42,52.92
$4N719 on TOP (solid shape): 81.15,30.62 81.15,30.22 81.15,30.22 81.15,26.91 80.91,26.66 80.91,24.88 80.85,24.82 80.06,24.82 79.89,24.99 79.89,25.88 79.18,26.59 79.18,30.63 79.23,30.67 81.1,30.67
$4N903 on TOP (solid shape): 17.53,65.52 17.53,64.51 17.4,64.38 16.89,64.38 16.38,64.89 16.38,65.52 16.51,65.65 17.4,65.65
$4N925 on TOP (solid shape): 12.77,67.49 12.91,67.49 13,67.4 13,63.74 12.98,63.72 12.19,63.72 11.99,63.72 11.96,63.74 11.96,65.87 11.79,66.04 10.74,66.04 10.35,65.65 10.35,65.1 9.76,64.51 5.15,64.51 4.74,64.92 4.74,67.57 5.18,68.01 12.25,68.01
$4N944 on TOP (solid shape): 10.92,79.62 10.92,76.15 9.85,75.08 8.39,75.08 7.75,74.43 7.75,70.34 7,69.6 5.57,69.6 4.95,70.22 4.95,78.54 4.96,78.54 4.96,79.74 5.63,80.41 10.13,80.41

Small or netless copper shapes (teardrops, artwork), in the pictures only: 7 on TOP, 7 on BOTTOM

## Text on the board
BOTTOM: HI3798MDMO1C-VERE ARTWORK BOTTOM
Ref Des/Silkscreen Bottom: 0295 | 0464 | 2014-08-12 | 2014-11-10 | 0483 | UPDATE | 02 | VER.E | 121251 | 122395 | D | E | HI3798MDMO1C-VERE SILKSCREEN BOTTOM
User.Comments: HI3798MDMO1C-VERE SOLDMASK TOP | HI3798MDMO1C-VERE SOLDMASK BOTTOM
TOP: HI3798MDMO1C-VERE ARTWORK TOP
Ref Des/Silkscreen Top: 121251 | 122395 | VER.E | 02 | UPDATE | 0464 | 0483 | 2014-08-12 | 2014-11-10 | 0295 | A | B | C | HI3798MDMO1C-VERE SILKSCREEN TOP | HI3798MDMO1C VER.E
DISPLAY_BOTTOM: HI3798MDMO1C-VERE PASTEMASK BOTTOM
DIMENSION: 121251 | 122395 | 02 | VER.E | UPDATE | 0464 | 0483 | 2014-08-12 | 2014-11-10 | 0295 | HI3798MDMO1C VER.E | Hi-Tg | 150 | C | Notes3: | 6.OBLONG VIAS:24 | For this PN,Soldermask should be covered at all required location and | no red solder(copper color) is allowed at BGA area | HI3798MDMO1C VER.E DRILL CHART
DISPLAY_TOP: HI3798MDMO1C-VERE PASTEMASK TOP
COMPVAL_TYPE_TOP: dia 3.5 | 61.97
User.12: 10 | 6 | 2 | 3 | 1 | 7 | 8 | 9 | PCB EDGE | 19 | 5 | 4 | J12 | S1 | A | dia 3.5 | 61.97 | 55 | BGA19X19 2-LAYERS
User.13: 10 | 6 | 2 | 3 | 1 | 7 | 8 | 9 | PCB EDGE | 19 | 5 | 4 | J12 | S1 | A | dia 3.5 | 55 | 61.97 | BGA19X19 2-LAYERS
User.20: FIGURE | SIZE | 8.0 | 10.0 | 20.0 | 22.0 | 26.0 | 32.0 | 36.0 | 38.0 | 40.0 | 45.0 | 52.0 | 142.0 | 43.0 | 71.0 | 135.0 | 55.0x31.0 | 60.0x32.0 | 82.0x36.0 | 83.0x31.0 | 96.0x26.0 | 96.0x30.0 | 98.0x47.0 | 98.0x59.0 | 105.0x36.0 | 116.0x30.0 | 118.0x79.0 | 118.0x87.0 | DRILL CHART: TOP to BOTTOM | ALL UNITS ARE IN MILS | PLATED | NON-PLATED | QTY | 873 | 1411 | 4 | 2 | 9 | 3 | 23 | 12 | 35 | 1
